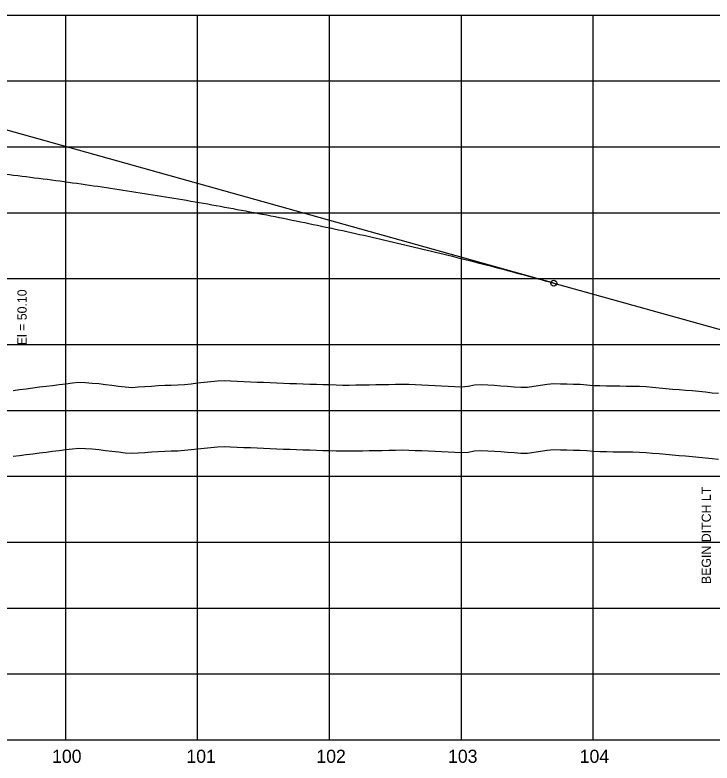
# Model space of a CAD drawing. Extents: x 2345490 to 2436403, y 465165 to 573888.
# Drawn here: x 2390283 to 2390812, y 557766 to 558334 of the extents above; entities that cross this region are included whole.
import ezdxf

# ---------------------------------------------------------------- set-up
doc = ezdxf.new("R2010")
doc.units = 0
for name, color, linetype in [('Old_Level_1', 7, 'Continuous'), ('Old_Level_2', 7, 'Continuous'), ('Old_Level_3', 7, 'Continuous'), ('Old_Level_57', 7, 'Continuous'), ('Old_Level_62', 7, 'Continuous'), ('Old_Level_63', 7, 'Continuous')]:
    doc.layers.add(name, color=color, linetype=linetype)

msp = doc.modelspace()

# ---------------------------------------------------------------- linework, layer by layer
at = {"layer": 'Old_Level_1'}
for points in [[(2390321.5425, 558004.3195), (2390326.5425, 558004.9245), (2390331.5425, 558005.52925), (2390336.5425, 558005.25675), (2390341.5425, 558004.84275), (2390346.5425, 558004.3935), (2390351.5425, 558003.78975), (2390356.5425, 558003.18625), (2390361.5425, 558002.583), (2390366.5425, 558001.98), (2390371.5425, 558001.5495), (2390376.5425, 558001.899), (2390381.5425, 558002.249), (2390386.5425, 558002.59925), (2390391.5425, 558002.94975), (2390396.5425, 558003.14275), (2390401.5425, 558003.28825), (2390406.5425, 558003.434), (2390411.5425, 558003.844), (2390416.5425, 558004.36875), (2390421.5425, 558004.893), (2390426.5425, 558005.41725), (2390431.5425, 558005.941), (2390436.5425, 558006.4645), (2390441.5425, 558006.6895), (2390446.5425, 558006.477), (2390451.5425, 558006.26475), (2390456.5425, 558006.052), (2390461.5425, 558005.8395), (2390466.5425, 558005.6265), (2390471.5425, 558005.4135), (2390476.5425, 558005.20025), (2390481.5425, 558004.987), (2390486.5425, 558004.74625), (2390491.5425, 558004.6055), (2390496.5425, 558004.44125), (2390501.5425, 558004.277), (2390506.5425, 558004.11275), (2390511.5425, 558003.949), (2390516.5425, 558003.7915), (2390521.5425, 558003.63425), (2390526.5425, 558003.47675), (2390531.5425, 558003.3195), (2390536.5425, 558003.35025), (2390541.5425, 558003.4305), (2390546.5425, 558003.511), (2390551.5425, 558003.59175), (2390556.5425, 558003.67275), (2390561.5425, 558003.75425), (2390566.5425, 558003.842), (2390571.5425, 558003.94975), (2390576.5425, 558004.05775), (2390581.5425, 558004.02725), (2390586.5425, 558003.78875), (2390591.5425, 558003.54625), (2390596.5425, 558003.30325), (2390601.5425, 558003.06025), (2390606.5425, 558002.817), (2390611.5425, 558002.5735), (2390616.5425, 558002.32975), (2390621.5425, 558002.086), (2390626.5425, 558002.47), (2390631.5425, 558003.431), (2390636.5425, 558003.6275), (2390641.5425, 558003.4635), (2390646.5425, 558003.15475), (2390651.5425, 558002.819), (2390656.5425, 558002.443), (2390661.5425, 558002.06725), (2390666.5425, 558001.6915), (2390671.5425, 558001.73675), (2390676.5425, 558002.42125), (2390681.5425, 558003.179), (2390686.5425, 558003.93775), (2390691.5425, 558004.41725), (2390696.5425, 558004.2915), (2390701.5425, 558004.16775), (2390706.5425, 558004.0455), (2390711.5425, 558003.92475), (2390716.5425, 558003.62175), (2390721.5425, 558003.0715), (2390726.5425, 558002.93125), (2390731.5425, 558002.8145), (2390736.5425, 558002.6995), (2390741.5425, 558002.65475), (2390746.5425, 558002.61075), (2390751.5425, 558002.568), (2390756.5425, 558002.526), (2390761.5425, 558002.25875), (2390766.5425, 558001.762), (2390771.5425, 558001.2655), (2390776.5425, 558000.77), (2390781.5425, 558000.2935), (2390786.5425, 557999.89575), (2390791.5425, 557999.499), (2390796.5425, 557999.10325), (2390801.5425, 557998.7085), (2390806.5425, 557998.14125), (2390811.5425, 557997.47), (2390816.5425, 557997.1175)], [(2390281.5425, 557999.26525), (2390286.5425, 557999.915), (2390291.5425, 558000.5645), (2390296.5425, 558001.192), (2390301.5425, 558001.89575), (2390306.5425, 558002.502), (2390311.5425, 558003.10825), (2390316.5425, 558003.714), (2390321.5425, 558004.3195)]]:
    msp.add_lwpolyline(points, dxfattribs=at)
at = {"layer": 'Old_Level_2'}
for q in [(2390054.19075, 558309.1715), (2390851.5425, 558085.913)]:
    msp.add_line((2390691.5425, 558130.713), q, dxfattribs=at)
msp.add_circle((2390691.5425, 558130.713), 2.25, dxfattribs=at)
msp.add_spline([(2389411.5425, 558169.65525), (2389437.1425, 558175.13775), (2389462.7425, 558180.36475), (2389488.3425, 558185.336), (2389513.9425, 558190.052), (2389539.5425, 558194.51225), (2389565.1425, 558198.717), (2389590.7425, 558202.666), (2389616.3425, 558206.3595), (2389641.9425, 558209.7975), (2389667.5425, 558212.98), (2389693.1425, 558215.90675), (2389718.7425, 558218.57825), (2389744.3425, 558220.994), (2389769.9425, 558223.154), (2389795.5425, 558225.05875), (2389821.1425, 558226.70775), (2389846.7425, 558228.10125), (2389872.3425, 558229.239), (2389897.9425, 558230.12125), (2389923.5425, 558230.74825), (2389949.1425, 558231.11925), (2389974.7425, 558231.235), (2390000.3425, 558231.095), (2390025.9425, 558230.6995), (2390051.5425, 558230.0485), (2390077.1425, 558229.14175), (2390102.7425, 558227.97975), (2390128.3425, 558226.562), (2390153.9425, 558224.8885), (2390179.5425, 558222.95975), (2390205.1425, 558220.77525), (2390230.7425, 558218.33525), (2390256.3425, 558215.6395), (2390281.9425, 558212.6885), (2390307.5425, 558209.48175), (2390333.1425, 558206.0195), (2390358.7425, 558202.3015), (2390384.3425, 558198.328), (2390409.9425, 558194.09925), (2390435.5425, 558189.6145), (2390461.1425, 558184.8745), (2390486.7425, 558179.87875), (2390512.3425, 558174.6275), (2390537.94275, 558169.12075), (2390563.54275, 558163.35825), (2390589.14275, 558157.34025), (2390614.74275, 558151.06675), (2390640.34275, 558144.53775), (2390665.94275, 558137.753), (2390691.54275, 558130.713)], degree=3, dxfattribs=at)
at = {"layer": 'Old_Level_57'}
for p, q in [((2381271.54275, 558334.11325), (2393041.55275, 558334.11325)), ((2390321.54225, 557784.21325), (2390321.54225, 558334.21325)), ((2390321.54225, 557784.11325), (2390321.54225, 558334.11325)), ((2390421.54225, 557784.21325), (2390421.54225, 558334.21325)), ((2390421.54225, 557784.11325), (2390421.54225, 558334.11325)), ((2390521.54225, 557784.21325), (2390521.54225, 558334.21325)), ((2390521.54225, 557784.11325), (2390521.54225, 558334.11325)), ((2390621.54225, 557784.21325), (2390621.54225, 558334.21325)), ((2390621.54225, 557784.11325), (2390621.54225, 558334.11325)), ((2390721.54225, 557784.21325), (2390721.54225, 558334.21325)), ((2390721.54225, 557784.11325), (2390721.54225, 558334.11325)), ((2381271.54275, 558284.11325), (2393041.55275, 558284.11325)), ((2381271.54275, 558234.11325), (2393041.55275, 558234.11325)), ((2381271.54275, 558184.11325), (2393041.55275, 558184.11325)), ((2381271.54275, 558134.11325), (2393041.55275, 558134.11325)), ((2381271.54275, 558084.11325), (2393041.55275, 558084.11325)), ((2381271.5425, 558034.11325), (2393041.55275, 558034.11325)), ((2381271.54275, 557984.11325), (2393041.55275, 557984.11325)), ((2381271.5425, 557934.11325), (2393041.55275, 557934.11325)), ((2381271.54275, 557884.11325), (2393041.55275, 557884.11325)), ((2381271.5425, 557834.11325), (2393041.55275, 557834.11325)), ((2381271.54275, 557784.11325), (2393041.55275, 557784.11325))]:
    msp.add_line(p, q, dxfattribs=at)
at = {"layer": 'Old_Level_62'}
for points in [[(2390321.5425, 558054.3255), (2390326.5425, 558054.9305), (2390331.5425, 558055.53525), (2390336.5425, 558055.26275), (2390341.5425, 558054.84875), (2390346.5425, 558054.3995), (2390351.5425, 558053.79575), (2390356.5425, 558053.19225), (2390361.5425, 558052.589), (2390366.5425, 558051.986), (2390371.5425, 558051.5555), (2390376.5425, 558051.905), (2390381.5425, 558052.255), (2390386.5425, 558052.60525), (2390391.5425, 558052.95575), (2390396.5425, 558053.14875), (2390401.5425, 558053.29425), (2390406.5425, 558053.44), (2390411.5425, 558053.85), (2390416.5425, 558054.37475), (2390421.5425, 558054.899), (2390426.5425, 558055.42325), (2390431.5425, 558055.947), (2390436.5425, 558056.4705), (2390441.5425, 558056.6955), (2390446.5425, 558056.483), (2390451.5425, 558056.27075), (2390456.5425, 558056.058), (2390461.5425, 558055.8455), (2390466.5425, 558055.6325), (2390471.5425, 558055.4195), (2390476.5425, 558055.20625), (2390481.5425, 558054.993), (2390486.5425, 558054.75225), (2390491.5425, 558054.6115), (2390496.5425, 558054.44725), (2390501.5425, 558054.283), (2390506.5425, 558054.11875), (2390511.5425, 558053.955), (2390516.5425, 558053.7975), (2390521.5425, 558053.64025), (2390526.5425, 558053.48275), (2390531.5425, 558053.3255), (2390536.5425, 558053.35625), (2390541.5425, 558053.4365), (2390546.5425, 558053.517), (2390551.5425, 558053.59775), (2390556.5425, 558053.67875), (2390561.5425, 558053.76025), (2390566.5425, 558053.848), (2390571.5425, 558053.95575), (2390576.5425, 558054.06375), (2390581.5425, 558054.03325), (2390586.5425, 558053.79475), (2390591.5425, 558053.55225), (2390596.5425, 558053.30925), (2390601.5425, 558053.06625), (2390606.5425, 558052.823), (2390611.5425, 558052.5795), (2390616.5425, 558052.33575), (2390621.5425, 558052.092), (2390626.5425, 558052.476), (2390631.5425, 558053.437), (2390636.5425, 558053.6335), (2390641.5425, 558053.4695), (2390646.5425, 558053.16075), (2390651.5425, 558052.825), (2390656.5425, 558052.449), (2390661.5425, 558052.07325), (2390666.5425, 558051.6975), (2390671.5425, 558051.74275), (2390676.5425, 558052.42725), (2390681.5425, 558053.185), (2390686.5425, 558053.94375), (2390691.5425, 558054.42325), (2390696.5425, 558054.2975), (2390701.5425, 558054.17375), (2390706.5425, 558054.0515), (2390711.5425, 558053.93075), (2390716.5425, 558053.62775), (2390721.5425, 558053.0775), (2390726.5425, 558052.93725), (2390731.5425, 558052.8205), (2390736.5425, 558052.7055), (2390741.5425, 558052.66075), (2390746.5425, 558052.61675), (2390751.5425, 558052.574), (2390756.5425, 558052.532), (2390761.5425, 558052.26475), (2390766.5425, 558051.768), (2390771.5425, 558051.2715), (2390776.5425, 558050.776), (2390781.5425, 558050.2995), (2390786.5425, 558049.90175), (2390791.5425, 558049.505), (2390796.5425, 558049.10925), (2390801.5425, 558048.7145), (2390806.5425, 558048.14725), (2390811.5425, 558047.476), (2390816.5425, 558047.1235)], [(2390281.5425, 558049.27125), (2390286.5425, 558049.921), (2390291.5425, 558050.5705), (2390296.5425, 558051.198), (2390301.5425, 558051.90175), (2390306.5425, 558052.508), (2390311.5425, 558053.11425), (2390316.5425, 558053.72), (2390321.5425, 558054.3255)]]:
    msp.add_lwpolyline(points, dxfattribs=at)
at = {"layer": 'Old_Level_63'}
msp.add_line((2381321.5425, 557784.113), (2393019.104, 557784.113), dxfattribs=at)

# ---------------------------------------------------------------- texts
at = {"layer": 'Old_Level_1'}
for s, p in [('100', (2390311.1715, 557766.613)), ('101', (2390413.01075, 557766.613)), ('102', (2390511.55925, 557766.613)), ('103', (2390611.394, 557766.613)), ('104', (2390711.2365, 557766.613))]:
    msp.add_text(s, height=10.000001, dxfattribs=at).set_placement(p)
at = {"layer": 'Old_Level_3'}
for s, height, p in [('El = 50.10', 7.000001, (2390291.8645, 558083.53113)), ('BEGIN DITCH LT', 7.0000005, (2390810.6686, 557902.31761))]:
    msp.add_text(s, height=height, rotation=90, dxfattribs=at).set_placement(p)

doc.saveas('drawing.dxf')
